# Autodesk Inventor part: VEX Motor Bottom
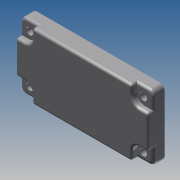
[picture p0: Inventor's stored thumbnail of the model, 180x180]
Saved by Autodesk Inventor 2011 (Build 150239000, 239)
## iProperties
Created: 2010-06
Part Number: VEX Motor Bottom
Document SubType Name: Modeling
Designer: Phil
Density: 1 g/cm^3
Author: Phil
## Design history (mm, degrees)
sketch "Sketch1"
  geometry: L1 (20, -8.5)-(20, 8.5) reference; L2 (18.5, 10)-(-18.5, 10) reference; L3 (-20, 8.5)-(-20, -8.5) reference; L4 (-18.5, -10)-(18.5, -10) reference; A1 r 1.5 centre (18.5, 8.5) between (20, 8.5) and (18.5, 10) reference; A2 r 1.5 centre (-18.5, 8.5) between (-18.5, 10) and (-20, 8.5) reference; A3 r 1.5 centre (-18.5, -8.5) between (-20, -8.5) and (-18.5, -10) reference; A4 r 1.5 centre (18.5, -8.5) between (18.5, -10) and (20, -8.5) reference; 1 further point
extrude "Extrusion1" new body sketch "Sketch1" distance "d0" = 5.0038; taper "d1" = 0 deg
sketch "Sketch2"
  geometry: L1 (-15.05, 10)-(-15.05, 7.495); L2 (-17.55, 4.995)-(-20, 4.995); L3 (-15.05, 10)-(-18.5, 10); L4 (-20, 4.995)-(-20, 8.5); A1 r 1.5 centre (-18.5, 8.5) between (-18.5, 10) and (-20, 8.5) reference
  constraints: 8 end point, 2 tangent, 1 parallel, 1 perpendicular, 2 other
extrude "Extrusion2" cut sketch "Sketch2" distance "d5" = 1.5875; taper "d6" = 0 deg
workplane "Work Plane2"
fillet "Fillet2" dims "d7" = 0.762
workplane "Work Plane3"
mirror "Mirror1"
mirror "Mirror2"
fillet "Fillet3" dims "d8" = 0.762
sketch "Sketch3"
  geometry: 2 further points
hole "Hole1" sketch "Sketch3" at (-17.266, 7.176) diameter "d9" = 2.1082; stored, may be unused: countersink angle "d13" = 82 deg, drill point angle "d15" = 118 deg; dims "d10" = 19.05, "d11" = 9.525, "d12" = 6.35, "d14" = 2.54
pattern_linear "Rectangular Pattern1" dims "d18" = 34.29, "d21" = 14.478
fillet "Fillet4" dims "d22" = 1.27
body "Solid1"
node "Reference1"
